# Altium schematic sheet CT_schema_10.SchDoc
size 274 x 160 mm
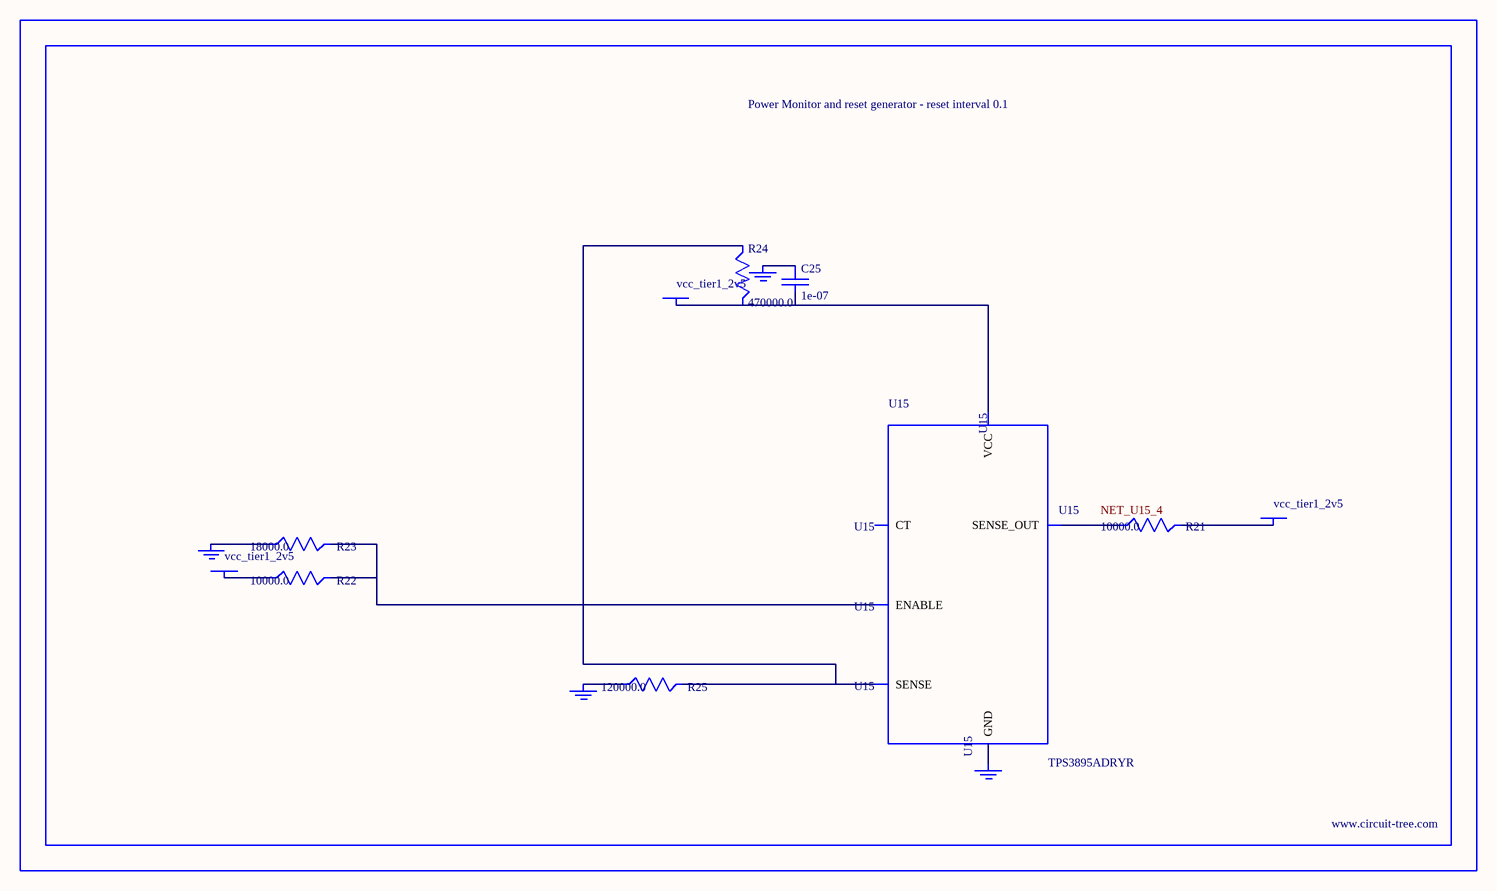
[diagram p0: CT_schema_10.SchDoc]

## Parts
BORDER9  (no value)
C25  1e-07  [C0402]
GND_INSTANCE_9_0  (no value)
GND_INSTANCE_9_1  (no value)
GND_INSTANCE_9_2  (no value)
GND_INSTANCE_9_3  (no value)
POWER_INSTANCE_9_0  vcc_tier1_2v5
POWER_INSTANCE_9_1  vcc_tier1_2v5
POWER_INSTANCE_9_2  vcc_tier1_2v5
R21  10000.0  [R0603]
R22  10000.0  [R0603]
R23  18000.0  [R0603]
R24  470000.0  [R0603]
R25  120000.0  [R0603]
U15  TPS3895ADRYR  [SON-6]

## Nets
NetC25_1: C25.1 GND_INSTANCE_9_2.0(GND)
NetC25_2: C25.2 POWER_INSTANCE_9_2.0(PWR) R24.2 U15.6(VCC)
NetGND_INSTANCE_9_0_0: GND_INSTANCE_9_0.0(GND) R23.1
NetGND_INSTANCE_9_1_0: GND_INSTANCE_9_1.0(GND) R25.1
NetGND_INSTANCE_9_3_0: GND_INSTANCE_9_3.0(GND) U15.2(GND)
NetPOWER_INSTANCE_9_0_0: POWER_INSTANCE_9_0.0(PWR) R22.1
NetPOWER_INSTANCE_9_1_0: POWER_INSTANCE_9_1.0(PWR) R21.2
NetR21_1: R21.1 U15.4(SENSE_OUT)
NetR22_2: R22.2 R23.2 U15.1(ENABLE)
NetR24_1: R24.1 R25.2 U15.3(SENSE)

Not connected (* = marked no-connect by the designer): U15 5(CT)

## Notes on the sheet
- Labels drawn without touching a wire or pin: NET_U15_4

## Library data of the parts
BORDER9 = BORDER_PAGE9
C25 = C0402C104K3RACTU
GND_INSTANCE_9_0-GND_INSTANCE_9_3 = GND
POWER_INSTANCE_9_0-POWER_INSTANCE_9_2 = PWR
R21 R22 = RC0603JR-0710KL
R23 = RC0603JR-0718KL
R24 = RC0603JR-07470KL
R25 = RC0603JR-07120KL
